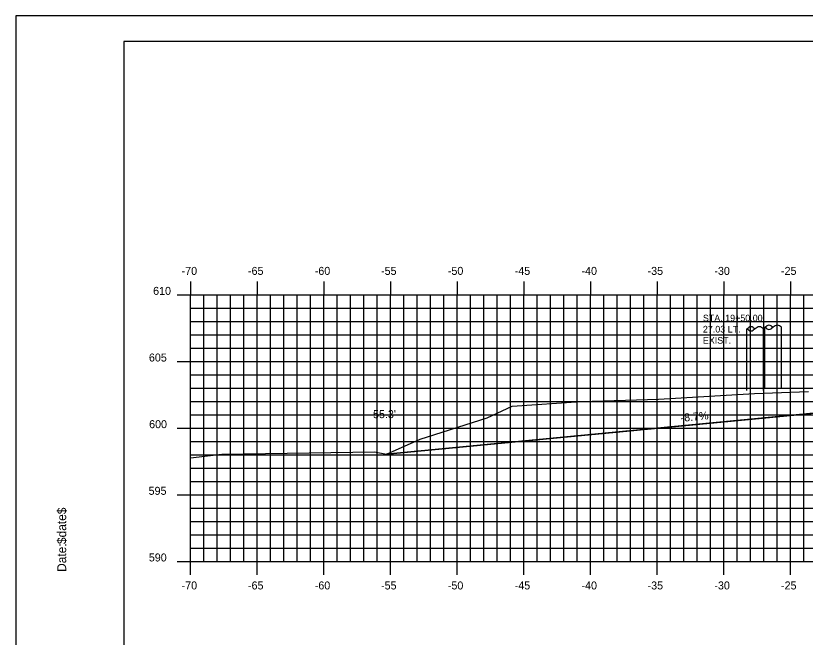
# Model space of a CAD drawing. Extents: x 1048141 to 1048311, y 780904 to 781014.
# Drawn here: x 1048140.6 to 1048199.8, y 780967.4 to 781014.1 of the extents above; entities that cross this region are included whole.
import ezdxf

# ---------------------------------------------------------------- set-up
doc = ezdxf.new("R2010")
doc.units = 0
for name, color, linetype in [('ANNOTATION', 7, 'Continuous'), ('D_Roadway_Centerline', 7, 'Continuous'), ('D_Roadway_SlopeLines', 7, 'Continuous'), ('D_Text_Monospaced', 7, 'Continuous'), ('Default', 7, 'Continuous'), ('H_V ANNOTATION', 7, 'Continuous'), ('MAJOR', 7, 'Continuous'), ('MINOR', 7, 'Continuous'), ('S_Roadway_Centerline', 7, 'Continuous'), ('S_Utilities_Pole_Brace3', 7, 'Continuous'), ('S_Utilities_Pole_Joint', 7, 'Continuous'), ('S_Utilities_Pole_Power', 7, 'Continuous')]:
    doc.layers.add(name, color=color, linetype=linetype)

msp = doc.modelspace()

# ---------------------------------------------------------------- linework, layer by layer
at = {"layer": 'D_Roadway_Centerline'}
msp.add_lwpolyline([(1048168.417, 780981.167), (1048206.016, 780984.768), (1048223.713, 780985.121), (1048277.445, 780984.047), (1048282.445, 780983.218)], dxfattribs=at)
at = {"layer": 'D_Roadway_SlopeLines'}
msp.add_line((1048206.016, 780984.768), (1048168.417, 780981.167), dxfattribs=at)
at = {"layer": 'Default'}
for p, q in [((1048308.713, 781012.114), (1048148.713, 781012.114)), ((1048148.713, 781012.114), (1048148.713, 780907.114))]:
    msp.add_line(p, q, dxfattribs=at)
msp.add_lwpolyline([(1048140.62, 780904.055), (1048310.62, 780904.055), (1048310.62, 781014.055), (1048140.62, 781014.055)], close=True, dxfattribs=at)
at = {"layer": 'MAJOR'}
for p, q in [((1048153.713, 780994.116), (1048153.713, 780993.114)), ((1048158.713, 780994.116), (1048158.713, 780993.114)), ((1048163.713, 780994.116), (1048163.713, 780993.114)), ((1048168.713, 780994.116), (1048168.713, 780993.114)), ((1048173.713, 780994.116), (1048173.713, 780993.114)), ((1048178.713, 780994.116), (1048178.713, 780993.114)), ((1048183.713, 780994.116), (1048183.713, 780993.114)), ((1048188.713, 780994.116), (1048188.713, 780993.114)), ((1048193.713, 780994.116), (1048193.713, 780993.114)), ((1048198.713, 780994.116), (1048198.713, 780993.114)), ((1048152.711, 780993.114), (1048153.713, 780993.114)), ((1048153.713, 780993.114), (1048293.713, 780993.114)), ((1048153.713, 780973.114), (1048153.713, 780993.114)), ((1048153.713, 780973.114), (1048153.713, 780993.114)), ((1048153.713, 780993.114), (1048293.713, 780993.114)), ((1048158.713, 780973.114), (1048158.713, 780993.114)), ((1048163.713, 780973.114), (1048163.713, 780993.114)), ((1048168.713, 780973.114), (1048168.713, 780993.114)), ((1048173.713, 780973.114), (1048173.713, 780993.114)), ((1048178.713, 780973.114), (1048178.713, 780993.114)), ((1048183.713, 780973.114), (1048183.713, 780993.114)), ((1048188.713, 780973.114), (1048188.713, 780993.114)), ((1048193.713, 780973.114), (1048193.713, 780993.114)), ((1048198.713, 780973.114), (1048198.713, 780993.114)), ((1048152.711, 780988.114), (1048153.713, 780988.114)), ((1048153.713, 780988.114), (1048293.713, 780988.114)), ((1048152.711, 780983.114), (1048153.713, 780983.114)), ((1048153.713, 780983.114), (1048293.713, 780983.114)), ((1048152.711, 780978.114), (1048153.713, 780978.114)), ((1048153.713, 780978.114), (1048293.713, 780978.114)), ((1048152.711, 780973.114), (1048153.713, 780973.114)), ((1048153.713, 780973.114), (1048293.713, 780973.114)), ((1048153.713, 780973.114), (1048293.713, 780973.114)), ((1048153.713, 780972.112), (1048153.713, 780973.114)), ((1048158.713, 780972.112), (1048158.713, 780973.114)), ((1048163.713, 780972.112), (1048163.713, 780973.114)), ((1048168.713, 780972.112), (1048168.713, 780973.114)), ((1048173.713, 780972.112), (1048173.713, 780973.114)), ((1048178.713, 780972.112), (1048178.713, 780973.114)), ((1048183.713, 780972.112), (1048183.713, 780973.114)), ((1048188.713, 780972.112), (1048188.713, 780973.114)), ((1048193.713, 780972.112), (1048193.713, 780973.114)), ((1048198.713, 780972.112), (1048198.713, 780973.114))]:
    msp.add_line(p, q, dxfattribs=at)
at = {"layer": 'MINOR'}
for p, q in [((1048154.713, 780973.114), (1048154.713, 780993.114)), ((1048155.713, 780973.114), (1048155.713, 780993.114)), ((1048156.713, 780973.114), (1048156.713, 780993.114)), ((1048157.713, 780973.114), (1048157.713, 780993.114)), ((1048159.713, 780973.114), (1048159.713, 780993.114)), ((1048160.713, 780973.114), (1048160.713, 780993.114)), ((1048161.713, 780973.114), (1048161.713, 780993.114)), ((1048162.713, 780973.114), (1048162.713, 780993.114)), ((1048164.713, 780973.114), (1048164.713, 780993.114)), ((1048165.713, 780973.114), (1048165.713, 780993.114)), ((1048166.713, 780973.114), (1048166.713, 780993.114)), ((1048167.713, 780973.114), (1048167.713, 780993.114)), ((1048169.713, 780973.114), (1048169.713, 780993.114)), ((1048170.713, 780973.114), (1048170.713, 780993.114)), ((1048171.713, 780973.114), (1048171.713, 780993.114)), ((1048172.713, 780973.114), (1048172.713, 780993.114)), ((1048174.713, 780973.114), (1048174.713, 780993.114)), ((1048175.713, 780973.114), (1048175.713, 780993.114)), ((1048176.713, 780973.114), (1048176.713, 780993.114)), ((1048177.713, 780973.114), (1048177.713, 780993.114)), ((1048179.713, 780973.114), (1048179.713, 780993.114)), ((1048180.713, 780973.114), (1048180.713, 780993.114)), ((1048181.713, 780973.114), (1048181.713, 780993.114)), ((1048182.713, 780973.114), (1048182.713, 780993.114)), ((1048184.713, 780973.114), (1048184.713, 780993.114)), ((1048185.713, 780973.114), (1048185.713, 780993.114)), ((1048186.713, 780973.114), (1048186.713, 780993.114)), ((1048187.713, 780973.114), (1048187.713, 780993.114)), ((1048189.713, 780973.114), (1048189.713, 780993.114)), ((1048190.713, 780973.114), (1048190.713, 780993.114)), ((1048191.713, 780973.114), (1048191.713, 780993.114)), ((1048192.713, 780973.114), (1048192.713, 780993.114)), ((1048194.713, 780973.114), (1048194.713, 780993.114)), ((1048195.713, 780973.114), (1048195.713, 780993.114)), ((1048196.713, 780973.114), (1048196.713, 780993.114)), ((1048197.713, 780973.114), (1048197.713, 780993.114)), ((1048199.713, 780973.114), (1048199.713, 780993.114)), ((1048153.713, 780992.114), (1048293.713, 780992.114)), ((1048153.713, 780992.114), (1048154.715, 780992.114)), ((1048153.713, 780991.114), (1048293.713, 780991.114)), ((1048153.713, 780991.114), (1048154.715, 780991.114)), ((1048153.713, 780990.114), (1048293.713, 780990.114)), ((1048153.713, 780990.114), (1048154.715, 780990.114)), ((1048153.713, 780989.114), (1048293.713, 780989.114)), ((1048153.713, 780989.114), (1048154.715, 780989.114)), ((1048153.713, 780987.114), (1048293.713, 780987.114)), ((1048153.713, 780987.114), (1048154.715, 780987.114)), ((1048153.713, 780986.114), (1048293.713, 780986.114)), ((1048153.713, 780986.114), (1048154.715, 780986.114)), ((1048153.713, 780985.114), (1048293.713, 780985.114)), ((1048153.713, 780985.114), (1048154.715, 780985.114)), ((1048153.713, 780984.114), (1048293.713, 780984.114)), ((1048153.713, 780984.114), (1048154.715, 780984.114)), ((1048153.713, 780982.114), (1048293.713, 780982.114)), ((1048153.713, 780982.114), (1048154.715, 780982.114)), ((1048153.713, 780981.114), (1048293.713, 780981.114)), ((1048153.713, 780981.114), (1048154.715, 780981.114)), ((1048153.713, 780980.114), (1048293.713, 780980.114)), ((1048153.713, 780980.114), (1048154.715, 780980.114)), ((1048153.713, 780979.114), (1048293.713, 780979.114)), ((1048153.713, 780979.114), (1048154.715, 780979.114)), ((1048153.713, 780977.114), (1048293.713, 780977.114)), ((1048153.713, 780977.114), (1048154.715, 780977.114)), ((1048153.713, 780976.114), (1048293.713, 780976.114)), ((1048153.713, 780976.114), (1048154.715, 780976.114)), ((1048153.713, 780975.114), (1048293.713, 780975.114)), ((1048153.713, 780975.114), (1048154.715, 780975.114)), ((1048153.713, 780974.114), (1048293.713, 780974.114)), ((1048153.713, 780974.114), (1048154.715, 780974.114))]:
    msp.add_line(p, q, dxfattribs=at)
at = {"layer": 'S_Roadway_Centerline'}
msp.add_lwpolyline([(1048153.713, 780980.881), (1048156.062, 780981.156), (1048167.504, 780981.346), (1048168.417, 780981.167), (1048170.942, 780982.29), (1048175.968, 780983.893), (1048177.829, 780984.772), (1048183.013, 780985.108), (1048188.804, 780985.291), (1048196.003, 780985.718), (1048200.047, 780985.855)], dxfattribs=at)
at = {"layer": 'S_Utilities_Pole_Brace3'}
for p, q in [((1048195.436, 780985.948), (1048195.439, 780990.567)), ((1048196.686, 780985.948), (1048196.689, 780990.567))]:
    msp.add_line(p, q, dxfattribs=at)
at = {"layer": 'S_Utilities_Pole_Joint'}
for p, q in [((1048195.436, 780990.567), (1048195.592, 780990.678)), ((1048195.592, 780990.457), (1048195.436, 780990.567)), ((1048195.905, 780990.678), (1048196.061, 780990.567)), ((1048196.061, 780990.567), (1048195.905, 780990.457)), ((1048196.218, 780990.678), (1048196.061, 780990.567)), ((1048196.686, 780990.567), (1048196.53, 780990.678)), ((1048196.78, 780990.68), (1048196.936, 780990.79)), ((1048196.936, 780990.569), (1048196.78, 780990.68)), ((1048197.249, 780990.79), (1048197.406, 780990.68)), ((1048197.406, 780990.68), (1048197.249, 780990.569)), ((1048197.562, 780990.79), (1048197.406, 780990.68)), ((1048198.03, 780990.68), (1048197.874, 780990.79))]:
    msp.add_line(p, q, dxfattribs=at)
for centre, start, end in [((1048195.749, 780990.457), 90, 125.26439), ((1048195.749, 780990.678), 234.73561, 270), ((1048195.749, 780990.457), 54.73561, 90), ((1048195.749, 780990.678), 270, 305.26439), ((1048196.374, 780990.457), 90, 125.26439), ((1048196.374, 780990.457), 54.73561, 90), ((1048197.093, 780990.569), 90, 125.26439), ((1048197.093, 780990.79), 234.73561, 270), ((1048197.093, 780990.569), 54.73561, 90), ((1048197.093, 780990.79), 270, 305.26439), ((1048197.718, 780990.569), 90, 125.26439), ((1048197.718, 780990.569), 54.73561, 90)]:
    msp.add_arc(centre, 0.271, start, end, dxfattribs=at)
at = {"layer": 'S_Utilities_Pole_Power'}
for p, q in [((1048196.78, 780986.06), (1048196.784, 780990.68)), ((1048198.03, 780986.06), (1048198.034, 780990.68))]:
    msp.add_line(p, q, dxfattribs=at)

# ---------------------------------------------------------------- texts
at = {"layer": 'ANNOTATION'}
for s, rotation, p in [("-55.3'", 360, (1048167.141, 780983.867)), ('-8.7%', 5.46395, (1048190.496, 780983.583))]:
    msp.add_text(s, height=0.6, rotation=rotation, dxfattribs=at).set_placement(p)
at = {"layer": 'D_Text_Monospaced'}
for s, height, p in [('STA. 19+50.00', 0.49998, (1048192.14, 780991.125)), ('27.03 LT.', 0.5, (1048192.14, 780990.291)), ('EXIST. ', 0.5, (1048192.14, 780989.451))]:
    msp.add_text(s, height=height, dxfattribs=at).set_placement(p)
at = {"layer": 'Default'}
for s, p in [('$date$', (1048144.398, 780974.419)), ('Date:', (1048144.398, 780972.331))]:
    msp.add_text(s, height=0.6696, rotation=90, dxfattribs=at).set_placement(p)
at = {"layer": 'H_V ANNOTATION'}
for s, p in [('-70', (1048153.055, 780994.614)), ('-65', (1048158.031, 780994.614)), ('-60', (1048163.039, 780994.614)), ('-55', (1048168.009, 780994.614)), ('-50', (1048173.017, 780994.614)), ('-45', (1048178.031, 780994.614)), ('-40', (1048183.039, 780994.614)), ('-35', (1048187.993, 780994.614)), ('-30', (1048193.001, 780994.614)), ('-25', (1048197.998, 780994.614)), ('610', (1048150.918, 780993.114)), ('605', (1048150.602, 780988.114)), ('600', (1048150.618, 780983.114)), ('595', (1048150.58, 780978.114)), ('590', (1048150.596, 780973.114)), ('-70', (1048153.055, 780971.014)), ('-65', (1048158.031, 780971.014)), ('-60', (1048163.039, 780971.014)), ('-55', (1048168.009, 780971.014)), ('-50', (1048173.017, 780971.014)), ('-45', (1048178.031, 780971.014)), ('-40', (1048183.039, 780971.014)), ('-35', (1048187.993, 780971.014)), ('-30', (1048193.001, 780971.014)), ('-25', (1048197.998, 780971.014))]:
    msp.add_text(s, height=0.6, dxfattribs=at).set_placement(p)
at = {"layer": 'MAJOR'}
msp.add_text('-', height=0.006, dxfattribs=at).set_placement((1048153.708, 780973.114))

doc.saveas('drawing.dxf')
